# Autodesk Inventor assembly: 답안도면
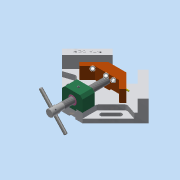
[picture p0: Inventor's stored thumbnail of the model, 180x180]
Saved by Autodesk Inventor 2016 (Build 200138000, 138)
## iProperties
Created: 2019-04
Part Number: 답안도면
Material: 일반
Document SubType Name: Assembly
Designer: 3sil_cad018
Author: 3sil_cad018
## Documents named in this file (11)
- C:\Users\3sil_cad018\Desktop\490408V1006\답안도면.iam
- C:\Users\3sil_cad018\Desktop\490408V1006\본체.ipt
- C:\Users\3sil_cad018\Desktop\490408V1006\리드스크류.ipt
- C:\Users\3sil_cad018\Desktop\490408V1006\멈춤나사 M4x5.ipt
- C:\Users\3sil_cad018\Desktop\490408V1006\멈춤나사 M4x10.ipt
- C:\Users\3sil_cad018\Desktop\490408V1006\볼트 M4x16.ipt
- C:\Users\3sil_cad018\Desktop\490408V1006\부시.ipt
- C:\Users\3sil_cad018\Desktop\490408V1006\서포트.ipt
- C:\Users\3sil_cad018\Desktop\490408V1006\조.ipt
- C:\Users\3sil_cad018\Desktop\490408V1006\평행 핀 2.5x24.ipt
- C:\Users\3sil_cad018\Desktop\490408V1006\핸들.ipt
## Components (1 placed, 1 different names)
1. 핸들:1 — 각도:2, 강체:2
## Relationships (2: Angle 1, WeldJoint 1)
- 각도:2 [Angle]: 핸들:1
- 강체:2 [WeldJoint]: 핸들:1
